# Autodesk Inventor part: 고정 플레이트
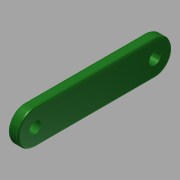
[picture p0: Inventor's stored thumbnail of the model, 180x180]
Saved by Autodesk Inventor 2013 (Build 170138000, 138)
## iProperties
Created: 2017-04
Part Number: 고정 플레이트
Material: 스테인리스강
Document SubType Name: Modeling
Designer: mduedu
Density: 1 g/cm^3
Author: mduedu
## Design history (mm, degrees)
sketch "스케치1"
  geometry: L1 (0, 17.5)-(0, -17.5); L2 (-5, 17.5)-(-5, -17.5); L3 (5, -17.5)-(5, 17.5); A1 r 5 centre (0, 17.5) between (5, 17.5) and (-5, 17.5); A2 r 5 centre (0, -17.5) between (-5, -17.5) and (5, -17.5); 2 further points
  constraints: 6 end point, 4 point on circle, 4 tangent, 3 coincident, 2 centre point, 1 midpoint, 1 parallel, 1 vertical
  dimensions: "d0" = 35 distance of L1.start L1.end; "d1" = 5 radius of A2
extrude "돌출1" new body sketch "스케치1" distance "d2" = 3; taper "d3" = 0 deg
fillet "모깎기1" dims "d4" = 0.5
sketch "스케치2"
  geometry: A1 r 5 centre (-17.5, 0) between (-17.5, 5) and (-17.5, -5) reference; A2 r 5 centre (17.5, 0) between (17.5, -5) and (17.5, 5) reference; 3 further points
  constraints: 2 coincident
sketch "스케치3"
  geometry: 3 further points
  constraints: 3 other
hole "구멍1" sketch "스케치3" at (-17.5, 0), (17.5, 0) diameter "d5" = 3.4; stored, may be unused: countersink angle "d9" = 90 deg, drill point angle "d11" = 0 deg; dims "d6" = 6, "d7" = 4, "d8" = 2, "d10" = 8
node "솔리드1"
